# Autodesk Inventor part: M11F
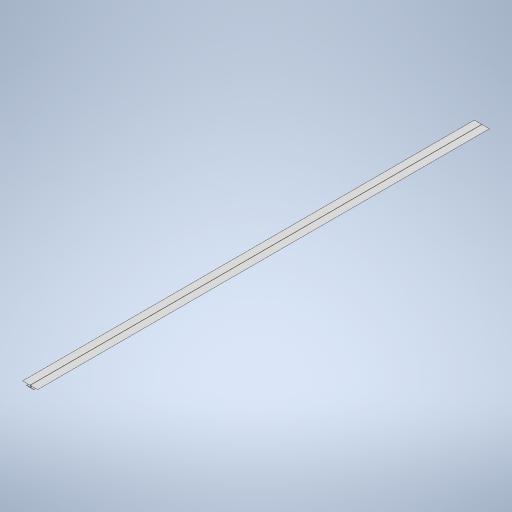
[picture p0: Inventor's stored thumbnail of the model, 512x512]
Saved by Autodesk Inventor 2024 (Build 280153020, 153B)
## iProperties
Created: 2023-09
Part Number: M11F
Material: Generic
Document SubType Name: Modeling
Designer: Olivier St-Arneault
Density: 1 g/cm^3
Appearance: Default
Author: Olivier St-Arneault
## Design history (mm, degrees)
sketch "Sketch1"
  geometry: L1 (-0.342, -1.521)-(-0.342, -13.596); L2 (-0.85, -1.521)-(-0.85, -13.596); L3 (-0.85, -13.596)-(-22.567, -13.596); L4 (-22.567, -13.596)-(-22.567, -14.104); L5 (-0.85, -14.104)-(-22.567, -14.104); L6 (0.166, -13.596)-(0.166, -1.521); L7 (22.391, -14.104)-(0.674, -14.104); L8 (22.391, -14.104)-(22.391, -13.596); L9 (22.391, -13.596)-(0.674, -13.596); L10 (0.674, -13.596)-(0.674, -1.521); L11 (24.042, -15.184)-(-24.218, -15.184); L12 (2.579, -12.644)-(24.042, -12.644); L13 (2.579, -13.152)-(24.042, -13.152); L14 (24.042, -14.676)-(-24.218, -14.676); L15 (-24.218, -13.152)-(-2.755, -13.152); L16 (-2.755, -13.152)-(-2.755, -12.644); L17 (-24.218, -12.644)-(-2.755, -12.644); L18 (2.579, -12.644)-(2.579, -13.152); L19 (0.674, -1.521)-(50.712, -1.521); L20 (0.674, -1.013)-(50.712, -1.013); L21 (50.712, -1.521)-(50.712, -1.013); L22 (-50.888, -1.013)-(-0.85, -1.013); L23 (-50.888, -1.013)-(-50.888, -1.521); L24 (-50.888, -1.521)-(-0.85, -1.521); A1 r 0.508 centre (-0.85, -13.596) between (-0.85, -14.104) and (-0.342, -13.596); A2 r 0.508 centre (0.674, -13.596) between (0.166, -13.596) and (0.674, -14.104); A3 r 1.27 centre (-24.218, -13.914) between (-24.218, -12.644) and (-24.218, -15.184); A4 r 1.27 centre (24.042, -13.914) between (24.042, -15.184) and (24.042, -12.644); A5 r 0.762 centre (-24.218, -13.914) between (-24.218, -13.152) and (-24.218, -14.676); A6 r 0.762 centre (24.042, -13.914) between (24.042, -14.676) and (24.042, -13.152); A7 r 0.508 centre (-0.85, -1.521) between (-0.342, -1.521) and (-0.85, -1.013); A8 r 0.508 centre (0.674, -1.521) between (0.674, -1.013) and (0.166, -1.521); 1 further point
  constraints: 48 end point, 16 point on circle, 8 centre point
extrude "Extrusion1" new body sketch "Sketch1" distance "d1" = 3048; taper "d2" = 0 deg
body "Solid1"
